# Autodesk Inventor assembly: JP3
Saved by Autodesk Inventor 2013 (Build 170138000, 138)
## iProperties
Created: 2021-02
Part Number: JP3
Document SubType Name: Assembly
Designer: Fede
Author: Fede
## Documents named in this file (2)
- C:\0000 FEDE\16GB\0000 INTERIOR\DE_TMP_BAS\BAS_DTON - demora conexion al energizar\DTON_MANUAL\img\INVENTOR\BAS_DTON - SIN R\JP3.iam
- C:\0000 FEDE\16GB\0000 INTERIOR\DE_TMP_BAS\BAS_DTON - demora conexion al energizar\DTON_MANUAL\img\INVENTOR\BAS_DTON - SIN R\bornera2x1.iam
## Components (1 placed, 1 different names)
1. bornera2x1:1 [sub-assembly]
